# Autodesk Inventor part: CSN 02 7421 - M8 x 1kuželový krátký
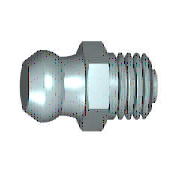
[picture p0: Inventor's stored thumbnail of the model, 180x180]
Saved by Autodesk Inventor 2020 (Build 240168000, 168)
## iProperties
Created: 2019-01
Part Number: CSN 02 7421 - M8 x 1kuželový krátký
Material: Ocel, měkká
Description: Přímé kulové mazací hlavice Typ A
Document SubType Name: Modeling
Standard: CSN 02 7421
Designer: doma
Standards Organization: CSN
Language: cs-CZ
Size Designation: M8 x 1kuželový krátký
Categories: <MemberInstance><Categories><Category DisplayName="Jiné díly" InternalName="5aa15e00-363f-49f2-933f-16f664388e3f" Mnemonic="OTHER"><Category DisplayName="Maznic
Density: 7.85 g/cm^3
Appearance: Pololeštěná
Mass: 5.50638 g
Surface Area: 4.7104 cm^2
Volume: 0.70145 cm^3
IsCustomPart: 0
Author: doma
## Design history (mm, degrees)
sketch "Náčrt1"
  geometry: L1 (-9.8, 0)-(-9.8, 2.25); L2 (-9.8, 2.25)-(-8.055, 3.194); L3 (-9.8, 0)-(6.2, 0); L4 (6.2, 0)-(6.2, 2); L5 (6.2, 2)-(5.5, 2); L6 (5.5, 2)-(5.5, 4); L7 (5.5, 4)-(0, 4); L8 (-13, 0)-(9.4, 0) reference; L9 (0, -1.655)-(0, 9.928) reference; L10 (-3, 4.5)-(0, 4.5); L11 (0, 4.5)-(0, 4); A1 r 3.25 centre (-7.455, 0) between (-5.573, 2.65) and (-8.055, 3.194); A2 r 6 centre (-7.665, 8.274) between (-5.573, 2.65) and (-3, 4.5)
  constraints: 18 end point, 5 perpendicular, 4 point on circle, 2 centre point, 2 parallel, 2 point on line, 1 collinear, 1 vertical
  dimensions: "d0" = 16 distance between parallel lines of L1 L4 (= GL); "d1" = 5.3 diameter of A1.start L3 (= KGB2); "d2" = 0.7 distance between parallel lines of L4 L6 (= PHH); "d3" = 4 diameter of L5 L3 (= 0.5 x NND); "d4" = 8 diameter of L7 L3 (= NND); "d5" = 6.5 dimension on A1 L3 (= KR); "d6" = 4.5 diameter of L1.end L3 (= KGB1); "d7" = 6 radius of A2 (= RBN); "d11" = 9 diameter of L10.start L3 (= SW); "d14" = 3 distance of L10.start L10.end (= KOH); "d15" = 5.5 distance between parallel lines of L6 L11 (= NLG); "d61" = 8.05479 distance from line of L9 L2.end (computed from KGB1, KR, PHH, GL, NLG, VERS); "d62" = 7.45479 distance from line of L9 A1.centre (computed from NLG, GL, PHH, KR, KGB1)
revolve "Těleso" sketch "Náčrt1" stored, may be unused: angle "d25" = 90 deg
sketch "Náčrt2"
  geometry: L1 (2.598, 4.5)-(5.196, 0); L2 (5.196, 0)-(2.598, -4.5); L3 (2.598, -4.5)-(-2.598, -4.5); L4 (-2.598, -4.5)-(-5.196, 0); L5 (-5.196, 0)-(-2.598, 4.5); L6 (-2.598, 4.5)-(2.598, 4.5); C1 r 4.5 at (0, 0) reference; 1 further point
  constraints: 12 end point, 1 coincident, 1 horizontal, 1 tangent, 11 other
extrude "Hlava" join sketch "Náčrt2" distance "d17" = 3 (= KOH); taper "d18" = 0 deg
sketch "Náčrt3"
  geometry: L1 (2.598, 5.196)-(3, 5.196); L2 (3, 5.196)-(3, 4.5); L3 (3, 4.5)-(2.598, 5.196); L4 (0.402, 5.196)-(0, 5.196); L5 (0, 5.196)-(0, 4.5); L6 (0, 4.5)-(0.402, 5.196); L7 (3.6, 0)-(-0.6, 0) reference; L8 (0, 5.196)-(0, 2.598) reference; L9 (0, 5.196)-(3, 5.196) reference; L10 (3, 3.897)-(3, 5.196) reference
  constraints: 12 end point, 4 collinear, 3 perpendicular, 1 horizontal
  dimensions: "d19" = 4.5 distance from line of L5.end L7 (= 0.5 x SW); "d20" = 4.5 distance from line of L2.end L7 (= 0.5 x SW); "d21" = 30 deg angle of L6 L5; "d22" = 30 deg angle of L2 L3
revolve "Zkosení1" sketch "Náčrt3" stored, may be unused: angle "d56" = 90 deg
body "Solid1"
fillet "Zaoblení1" dims "d8" = 0.2 (= RR)
feature "Závit1" dims "d9" = 4.88655 (= NLG - GAL), "d10" = 0
chamfer "Zkosení2" distance "d23" = 0.61345 (= -0.5 x GD1 + 0.5 x NND); stored, may be unused: angle "d24" = 45 deg, second distance "d59" = 0.61345 (= -0.5 x GD1 + 0.5 x NND)
other parameters: "NLG" = 5.5 [user parameter; used in 4 equation terms], "GL" = 16 [user parameter; used in 3 equation terms], "NND" = 8 [user parameter; used in 4 equation terms], "KGB1" = 4.5 [user parameter; used in 3 equation terms], "KGB2" = 5.3 [user parameter; used in 1 equation term], "VERS" = 0.6 [user parameter; used in 1 equation term], "KR" = 6.5 [user parameter; used in 3 equation terms], "RBN" = 6 [user parameter; used in 1 equation term], "SW" = 9 [user parameter; used in 3 equation terms], "KOH" = 3 [user parameter; used in 2 equation terms], "GAL" = 0.61345 (= 0.61345 x PTC) [user parameter; used in 1 equation term], "FAWI" = 45 deg [user parameter], "PHH" = 0.7 [user parameter; used in 3 equation terms], "GD1" = 6.7731 (= THREADDIA - 1.2269 x PTC) [user parameter; used in 2 equation terms], "RR" = 0.2 [user parameter; used in 1 equation term], "d12" = 0, "d13" = 0, "GUL" = 0.61345 (= 0.61345 x PTC) [user parameter], "DULO" = 1.5 [user parameter], "PTC" = 1 [user parameter; used in 4 equation terms], "GEL" = 5.5 [user parameter], "THREADDIA" = 8 [user parameter; used in 1 equation term], "TOA" = 30 deg [user parameter]
